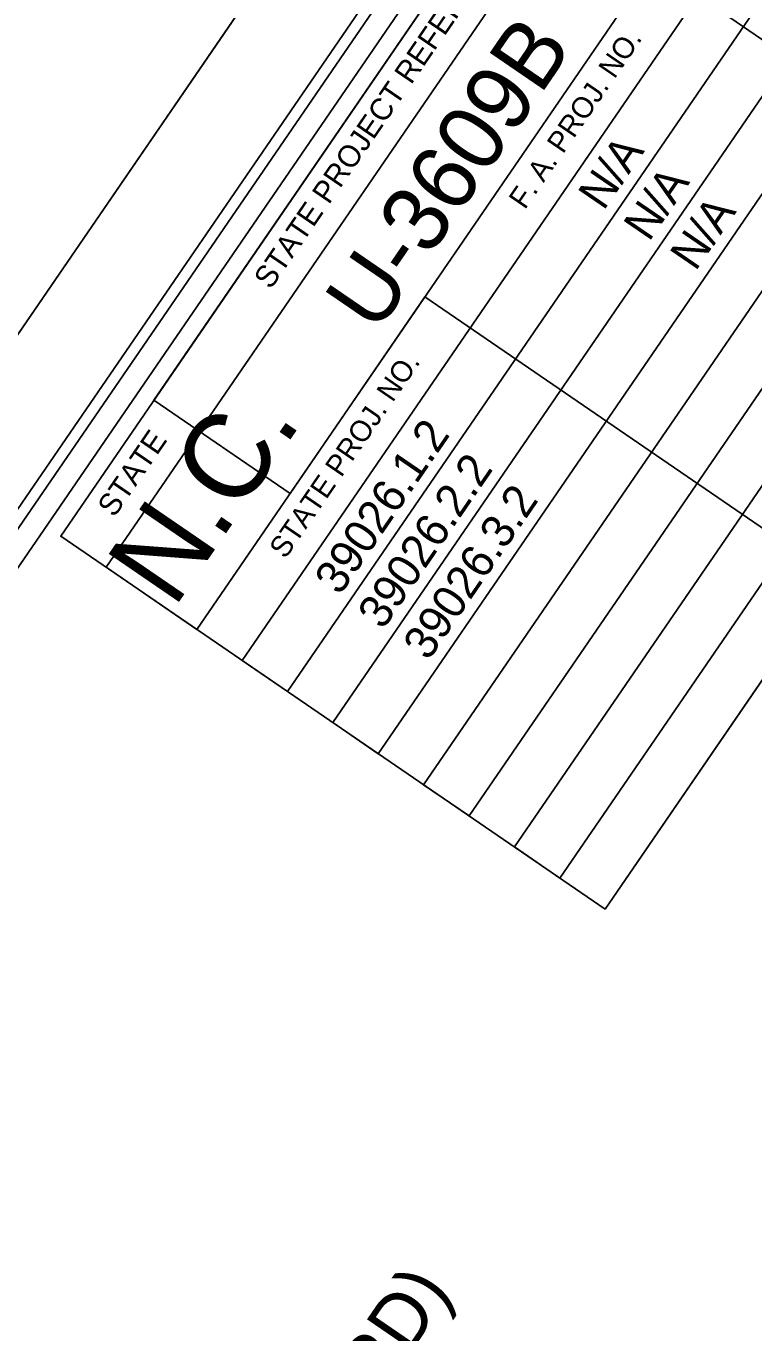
# Model space of a CAD drawing. Extents: x 2312641 to 2338852, y 590461 to 618614.
# Drawn here: x 2324050 to 2326365, y 612333 to 616493 of the extents above; entities that cross this region are included whole.
import ezdxf

# ---------------------------------------------------------------- set-up
doc = ezdxf.new("R2010")
doc.units = 0
for name, color, linetype in [('Exist Other Culture Sign Post Text', 7, 'Continuous'), ('Exist Property Iron Pin Cogo Number', 7, 'Continuous'), ('Exist Utilities Power Joint Use Telephone CELL', 7, 'Continuous'), ('Exist Utilities Power Joint Use Telephone Text', 7, 'Continuous'), ('Exist Vegetation Woods Line Text', 7, 'Continuous')]:
    doc.layers.add(name, color=color, linetype=linetype)

msp = doc.modelspace()

# ---------------------------------------------------------------- linework, layer by layer
at = {"layer": 'Exist Other Culture Sign Post Text'}
msp.add_line((2312821.5, 599166.9), (2326149.2, 618614.2), dxfattribs=at)
at = {"layer": 'Exist Property Iron Pin Cogo Number'}
for points in [[(2326224.4, 618104.7), (2314510.8, 601013.1)], [(2326336, 618045), (2324159.7, 614869.1), (2325891.8, 613682.1), (2326617.3, 614740.4), (2325318.1, 615630.7), (2324889.5, 615005.4), (2324456.3, 615302.3), (2325742.6, 617178.9)], [(2326242.4, 618007.3), (2315004.1, 601608.8)], [(2326769, 617748.2), (2324592.6, 614572.4), (2324303.9, 614770.3), (2326480.3, 617946.1)], [(2327057.9, 617550.2), (2324881.4, 614374.5), (2324737.1, 614473.4), (2326913.5, 617649.2)], [(2327346.4, 617352.5), (2325170, 614176.7), (2325025.8, 614275.5), (2327202.1, 617451.4)], [(2327635.3, 617154.5), (2325458.9, 613978.9), (2325314.4, 614077.8), (2327490.8, 617253.6)], [(2327924, 616956.7), (2325747.4, 613781), (2325603.2, 613879.8), (2327779.7, 617055.6)], [(2325891.8, 613682.1), (2328068.2, 616857.8)], [(2326043.3, 616689.2), (2327342.5, 615798.9), (2328068.2, 616857.8)]]:
    msp.add_lwpolyline(points, dxfattribs=at)
at = {"layer": 'Exist Utilities Power Joint Use Telephone CELL'}
msp.add_lwpolyline([(2326149.2, 618614.2), (2312821.5, 599166.9), (2325524.4, 590461.2), (2338852.2, 609908.5)], close=True, dxfattribs=at)
at = {"layer": 'Exist Utilities Power Joint Use Telephone Text'}
msp.add_lwpolyline([(2325368.2, 590788.9), (2338557.5, 610034.1), (2326372.9, 618384.6), (2313183.6, 599139.4)], close=True, dxfattribs=at)

# ---------------------------------------------------------------- texts
at = {"layer": 'Exist Property Iron Pin Cogo Number'}
for s, height, p in [('STATE PROJECT REFERENCE NO.', 69.997, (2324827.7, 615652)), ('F. A. PROJ. NO.', 67.2, (2325636.6, 615906.3)), ('STATE PROJ. NO.', 67.2, (2324874.4, 614794.2)), ('N.C.', 270.9, (2324519.4, 614635.3)), ('STATE', 70, (2324330.1, 614926.2))]:
    msp.add_text(s, height=height, rotation=55.5761, dxfattribs=at).set_placement(p)
at = {"layer": 'Exist Vegetation Woods Line Text'}
for s, height, p in [('U-3609B', 210, (2325164.4, 615510.6)), ('N/A', 105, (2325886.9, 615902.6)), ('N/A', 105, (2326031.3, 615803.7)), ('N/A', 105, (2326179.2, 615709.9)), ('39026.1.2', 105, (2325047.7, 614677.7)), ('39026.2.2', 105, (2325184.9, 614568.4)), ('39026.3.2', 105, (2325329.3, 614469.5)), ('U.S. 13 (BERKELEY BLVD) FROM S.R. 1003 (NEW HOPE RD)', 175.001, (2321636.1, 606962.2))]:
    msp.add_text(s, height=height, rotation=55.5761, dxfattribs=at).set_placement(p)

doc.saveas('drawing.dxf')
